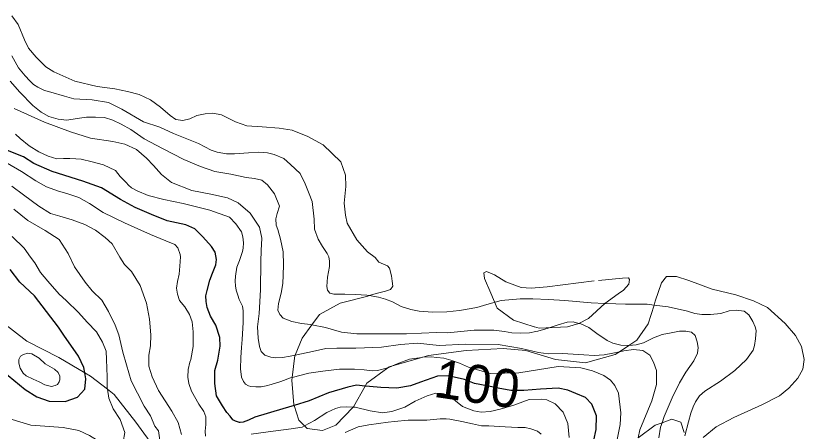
# Model space of a CAD drawing. Extents: x 474.5 to 500, y 7345.7 to 7373.4.
# Drawn here: x 486.724 to 488.382, y 7367.094 to 7367.969 of the extents above; entities that cross this region are included whole.
import ezdxf
from ezdxf.enums import TextEntityAlignment as Align

# ---------------------------------------------------------------- set-up
doc = ezdxf.new("R2010")
doc.units = 0
doc.header["$LTSCALE"] = 0.032
doc.linetypes.add('SHORT_DASHED', pattern=[2.7, 1.5, -1.2])
for name, color, linetype, lineweight in [('1', 7, 'Continuous', 25), ('16', 7, 'SHORT_DASHED', 13), ('2', 7, 'Continuous', 13)]:
    doc.layers.add(name, color=color, linetype=linetype, lineweight=lineweight)
doc.layers.add('61', color=7, linetype='Continuous')

msp = doc.modelspace()

# ---------------------------------------------------------------- linework, layer by layer
at = {"layer": '1'}
for points in [[(487.9397, 7367.0753), (487.9444, 7367.0977), (487.9451, 7367.127), (487.9356, 7367.1516), (487.9219, 7367.1652), (487.9015, 7367.1734), (487.8851, 7367.1809), (487.8647, 7367.185), (487.8272, 7367.1829), (487.7925, 7367.1802), (487.7652, 7367.1802), (487.7386, 7367.185), (487.7148, 7367.1897), (487.6888, 7367.1947), (487.6677, 7367.2034), (487.633, 7367.2109), (487.6112, 7367.2102), (487.575, 7367.1979), (487.5539, 7367.1897), (487.5253, 7367.185), (487.4919, 7367.1863), (487.468, 7367.1884), (487.4586, 7367.1893), (487.4408, 7367.1911), (487.4224, 7367.187), (487.3815, 7367.1748), (487.3406, 7367.1584), (487.309, 7367.1487), (487.2854, 7367.1414), (487.2268, 7367.1236), (487.2132, 7367.1175), (487.2023, 7367.1134), (487.1954, 7367.1127), (487.1941, 7367.1127), (487.1859, 7367.1155), (487.1804, 7367.1182), (487.175, 7367.1257), (487.168, 7367.1335), (487.1586, 7367.1475), (487.1457, 7367.1686), (487.1423, 7367.1945), (487.1423, 7367.2225), (487.1491, 7367.2436), (487.1539, 7367.2736), (487.1532, 7367.292), (487.1443, 7367.3179), (487.1334, 7367.3363), (487.1266, 7367.3547), (487.1239, 7367.3676), (487.1232, 7367.3792), (487.1266, 7367.3908), (487.1321, 7367.4126), (487.1375, 7367.4269), (487.1443, 7367.4446), (487.1457, 7367.4562), (487.143, 7367.4712), (487.1355, 7367.4835), (487.1171, 7367.5039), (487.1007, 7367.5203), (487.0816, 7367.5291), (487.0421, 7367.5373), (487.0094, 7367.551), (486.9746, 7367.5653), (486.944, 7367.5823), (486.9037, 7367.6068), (486.8649, 7367.6212), (486.8002, 7367.6409), (486.762, 7367.658), (486.7402, 7367.6723), (486.6809, 7367.6954)], [(486.6958, 7367.2218), (486.7433, 7367.1823), (486.7683, 7367.1667), (486.7941, 7367.1578), (486.8278, 7367.157), (486.8539, 7367.1658), (486.8688, 7367.183), (486.8714, 7367.2045), (486.8689, 7367.2175), (486.8667, 7367.2284), (486.8555, 7367.2526), (486.8246, 7367.2963), (486.8137, 7367.3135), (486.7631, 7367.3793), (486.7321, 7367.4081), (486.712, 7367.4346)]]:
    msp.add_lwpolyline(points, dxfattribs=at)
at = {"layer": '16'}
for points in [[(487.4637, 7367.472), (487.441, 7367.4973), (487.421, 7367.5321), (487.417, 7367.5494), (487.4143, 7367.5748), (487.4183, 7367.6095), (487.4175, 7367.6333), (487.4076, 7367.6616), (487.3702, 7367.6976), (487.3382, 7367.715), (487.3048, 7367.7283), (487.2781, 7367.7323), (487.2421, 7367.735), (487.21, 7367.7377), (487.186, 7367.7457), (487.1566, 7367.7604), (487.1379, 7367.7644), (487.1219, 7367.763), (487.1045, 7367.759), (487.0898, 7367.7524), (487.0752, 7367.7484), (487.0605, 7367.751), (487.0485, 7367.759), (487.0284, 7367.7764), (487.0071, 7367.7924), (486.983, 7367.8031), (486.959, 7367.8098), (486.9323, 7367.8151), (486.8949, 7367.8205), (486.8482, 7367.8311), (486.8041, 7367.8512), (486.7868, 7367.8618), (486.7667, 7367.8819), (486.7507, 7367.9006), (486.7419, 7367.9186), (486.7287, 7367.9511), (486.7154, 7367.9692)], [(487.5057, 7367.4425), (487.4873, 7367.4503), (487.4797, 7367.46), (487.4637, 7367.472)], [(488.0926, 7367.4199), (488.0819, 7367.407), (488.0689, 7367.3681), (488.0663, 7367.3598), (488.0538, 7367.3206), (488.03, 7367.286), (488.013, 7367.2747), (487.9935, 7367.2616), (487.9847, 7367.2558), (487.922, 7367.2385), (487.8594, 7367.245), (487.7968, 7367.2644), (487.7493, 7367.2688), (487.6715, 7367.2644), (487.5916, 7367.2536), (487.5781, 7367.2497), (487.5164, 7367.2319), (487.5095, 7367.2299), (487.5063, 7367.2275), (487.462, 7367.1953), (487.4586, 7367.1893), (487.4339, 7367.1456), (487.4334, 7367.145), (487.3972, 7367.1068), (487.3691, 7367.096), (487.3367, 7367.1003), (487.3314, 7367.1056), (487.3194, 7367.1176), (487.309, 7367.1487), (487.3086, 7367.15), (487.3043, 7367.2018), (487.305, 7367.2074), (487.3108, 7367.2536), (487.3112, 7367.2545), (487.3259, 7367.2904), (487.3466, 7367.3184), (487.3626, 7367.34), (487.4058, 7367.3638), (487.4641, 7367.3789), (487.4673, 7367.3798), (487.4849, 7367.3849), (487.5016, 7367.3892), (487.5119, 7367.3929), (487.5166, 7367.3995), (487.5152, 7367.4103), (487.5138, 7367.4212), (487.5096, 7367.438), (487.5057, 7367.4425)], [(487.7227, 7367.3851), (487.7094, 7367.4159), (487.7083, 7367.4276), (487.7137, 7367.4307)], [(487.7137, 7367.4307), (487.7307, 7367.4239), (487.7548, 7367.4092), (487.7868, 7367.3972), (487.8082, 7367.3959), (487.8415, 7367.3985), (487.9497, 7367.4119), (487.9999, 7367.4163), (488.0126, 7367.4174)], [(488.0126, 7367.4174), (488.0148, 7367.414), (488.0132, 7367.4038), (488.0023, 7367.391), (487.9907, 7367.3833), (487.9626, 7367.3635)], [(488.17, 7367.0808), (488.1967, 7367.1035), (488.2341, 7367.1235), (488.2928, 7367.1502), (488.3302, 7367.1689), (488.3502, 7367.1849), (488.3689, 7367.2063), (488.3796, 7367.225), (488.3823, 7367.245), (488.3769, 7367.273), (488.3636, 7367.2957), (488.3422, 7367.3211), (488.3048, 7367.3545), (488.2755, 7367.3692), (488.2381, 7367.3812), (488.1887, 7367.3932), (488.1393, 7367.4119), (488.1139, 7367.4199), (488.0926, 7367.4199)], [(487.8142, 7367.3138), (487.7706, 7367.3283), (487.7367, 7367.3532), (487.7227, 7367.3851)], [(487.9626, 7367.3635), (487.9285, 7367.3314), (487.9085, 7367.3214)], [(486.6974, 7367.3228), (486.7471, 7367.2839), (486.814, 7367.2493), (486.8689, 7367.2175), (486.881, 7367.2104), (486.9165, 7367.1826), (486.9306, 7367.1716), (486.976, 7367.1132), (487.0235, 7367.0484), (487.0309, 7367.0365), (487.0575, 7366.9935), (487.0831, 7366.9551), (487.1102, 7366.9431), (487.1531, 7366.9356), (487.1606, 7366.9343), (487.2379, 7366.9445), (487.3718, 7366.9623), (487.4094, 7366.9711), (487.4378, 7366.976), (487.5197, 7366.9903)], [(487.9085, 7367.3214), (487.8843, 7367.3138), (487.8247, 7367.3115), (487.815, 7367.3138), (487.8142, 7367.3138)], [(488.0331, 7367.0803), (488.0689, 7367.1068), (488.0832, 7367.1121), (488.1035, 7367.1197), (488.1229, 7367.1132), (488.1294, 7367.0916)]]:
    msp.add_lwpolyline(points, dxfattribs=at)
at = {"layer": '2'}
for points in [[(486.7151, 7367.8848), (486.7292, 7367.8593), (486.7434, 7367.8428), (486.753, 7367.8322), (486.761, 7367.8246), (486.7699, 7367.8189), (486.7842, 7367.812), (486.7974, 7367.808), (486.8259, 7367.8), (486.8461, 7367.7944), (486.8847, 7367.7924), (486.9185, 7367.7864), (486.947, 7367.7722), (486.9925, 7367.746), (487.027, 7367.7348), (487.0558, 7367.7215), (487.1083, 7367.7003), (487.1345, 7367.686), (487.1474, 7367.6817), (487.1673, 7367.6781), (487.184, 7367.6781), (487.2135, 7367.6804), (487.235, 7367.6821), (487.2533, 7367.6808), (487.2672, 7367.6771), (487.2874, 7367.6685), (487.3018, 7367.6562), (487.3223, 7367.6367), (487.3326, 7367.6155), (487.3412, 7367.5943), (487.3473, 7367.5781), (487.3513, 7367.541), (487.352, 7367.5201), (487.3601, 7367.4986), (487.3687, 7367.4834), (487.379, 7367.4688), (487.3823, 7367.4618), (487.384, 7367.4522), (487.384, 7367.4413), (487.3793, 7367.4187), (487.3783, 7367.3992), (487.3795, 7367.3916), (487.3844, 7367.385), (487.3927, 7367.383), (487.4026, 7367.383), (487.4159, 7367.383), (487.4381, 7367.3823), (487.4619, 7367.3806), (487.4673, 7367.3798), (487.4868, 7367.3767), (487.5012, 7367.3727), (487.5161, 7367.3668), (487.5343, 7367.3572), (487.5545, 7367.3505), (487.5724, 7367.3469), (487.6009, 7367.3452), (487.6302, 7367.3459), (487.657, 7367.3485), (487.6935, 7367.3548), (487.7148, 7367.361), (487.745, 7367.3697), (487.7844, 7367.3733)], [(488.1572, 7367.2824), (488.1528, 7367.2956), (488.1453, 7367.3027), (488.133, 7367.3053), (488.1202, 7367.3053), (488.1021, 7367.3018), (488.0836, 7367.2978), (488.0651, 7367.2908), (488.0439, 7367.2802), (488.0289, 7367.2762), (488.013, 7367.2747), (488.0113, 7367.2745), (487.9968, 7367.2758), (487.98, 7367.2798), (487.9677, 7367.2855), (487.9461, 7367.3), (487.9293, 7367.3128), (487.9126, 7367.3203), (487.9085, 7367.3214), (487.8962, 7367.3247), (487.8839, 7367.3243), (487.8645, 7367.3181), (487.8433, 7367.3111), (487.8217, 7367.3049), (487.818, 7367.3042), (487.8041, 7367.3014), (487.7856, 7367.3005), (487.7671, 7367.3018), (487.7517, 7367.304), (487.7292, 7367.3071), (487.6877, 7367.3071), (487.6322, 7367.3014), (487.6084, 7367.3022), (487.5453, 7367.2996), (487.4783, 7367.2992), (487.4409, 7367.2996), (487.4091, 7367.3031), (487.3756, 7367.3124), (487.3466, 7367.3184), (487.3439, 7367.319), (487.3245, 7367.3212), (487.3042, 7367.3256), (487.2861, 7367.3322), (487.279, 7367.34), (487.2747, 7367.349), (487.2764, 7367.3635), (487.2817, 7367.3851), (487.2853, 7367.4054), (487.2861, 7367.4226), (487.287, 7367.4446), (487.2861, 7367.472), (487.2804, 7367.4984), (487.2747, 7367.5191), (487.2716, 7367.5284), (487.2707, 7367.5416), (487.2738, 7367.5531), (487.2786, 7367.5685), (487.2681, 7367.5941), (487.2535, 7367.6135), (487.2412, 7367.6227), (487.2262, 7367.6267), (487.2081, 7367.6289), (487.1759, 7367.6359), (487.1424, 7367.6412), (487.112, 7367.6518), (487.0772, 7367.6664), (487.0322, 7367.6897), (486.9939, 7367.71), (486.9661, 7367.7294), (486.9454, 7367.7409), (486.9277, 7367.7492), (486.9101, 7367.755), (486.8916, 7367.7559), (486.8726, 7367.7559), (486.8532, 7367.7528), (486.8312, 7367.7492), (486.8131, 7367.7514), (486.7933, 7367.7572), (486.7774, 7367.766), (486.7598, 7367.7805), (486.732, 7367.8083), (486.7117, 7367.8312)], [(487.9797, 7367.2584), (487.9613, 7367.2553), (487.9402, 7367.254), (487.9187, 7367.2553), (487.8738, 7367.258), (487.8446, 7367.2575), (487.8236, 7367.2602), (487.7877, 7367.2688), (487.7387, 7367.2768), (487.6696, 7367.2777), (487.6144, 7367.2746), (487.5691, 7367.2795), (487.5327, 7367.2768), (487.4928, 7367.2715), (487.4389, 7367.2692), (487.399, 7367.2692), (487.3757, 7367.2688), (487.3478, 7367.2625), (487.3112, 7367.2545), (487.3007, 7367.2522), (487.285, 7367.2495), (487.2698, 7367.2486), (487.2603, 7367.2499), (487.2478, 7367.2548), (487.2397, 7367.2625), (487.2365, 7367.2724), (487.2339, 7367.2903), (487.2325, 7367.3141), (487.2356, 7367.3419), (487.2388, 7367.3917), (487.2392, 7367.4519), (487.2401, 7367.4748), (487.241, 7367.5008), (487.2361, 7367.5237), (487.2168, 7367.5533), (487.1912, 7367.5753), (487.1688, 7367.5856), (487.1338, 7367.5937), (487.0938, 7367.6009), (487.0516, 7367.6179), (487.0301, 7367.635), (487.0131, 7367.6538), (486.9987, 7367.6695), (486.9776, 7367.6875), (486.9529, 7367.6991), (486.9278, 7367.7045), (486.8811, 7367.7117), (486.8389, 7367.7247), (486.7842, 7367.7449), (486.72, 7367.7741)], [(487.6391, 7367.2439), (487.6244, 7367.2479), (487.6093, 7367.2496), (487.5976, 7367.2509), (487.5795, 7367.2499), (487.5781, 7367.2497), (487.5518, 7367.2459), (487.526, 7367.2362), (487.5164, 7367.2319), (487.5073, 7367.2278), (487.5063, 7367.2275), (487.4845, 7367.2221), (487.4738, 7367.2215), (487.4568, 7367.2235), (487.436, 7367.2248), (487.4049, 7367.2252), (487.3698, 7367.2211), (487.3403, 7367.2168), (487.305, 7367.2074), (487.3015, 7367.2065), (487.2811, 7367.1988), (487.2613, 7367.1927), (487.2506, 7367.1901), (487.2399, 7367.1881), (487.2289, 7367.1877), (487.2185, 7367.1884), (487.2131, 7367.1897), (487.2071, 7367.1931), (487.2028, 7367.1988), (487.1984, 7367.2078), (487.1964, 7367.2255), (487.1971, 7367.2493), (487.1984, 7367.2707), (487.2001, 7367.2878), (487.2023, 7367.3232), (487.2023, 7367.3476), (487.2006, 7367.3576), (487.1939, 7367.372), (487.1906, 7367.3807), (487.1876, 7367.3911), (487.1859, 7367.4008), (487.1852, 7367.4105), (487.1856, 7367.4209), (487.189, 7367.4397), (487.1945, 7367.4541), (487.2006, 7367.4725), (487.2022, 7367.4799), (487.2026, 7367.4913), (487.2016, 7367.5036), (487.1982, 7367.514), (487.1865, 7367.5308), (487.173, 7367.5451), (487.1322, 7367.5595), (487.076, 7367.5736), (487.0352, 7367.582), (487.0023, 7367.591), (486.9792, 7367.6004), (486.9672, 7367.6068), (486.9608, 7367.6125), (486.9558, 7367.6181), (486.9434, 7367.6305), (486.9332, 7367.6431), (486.9083, 7367.6551), (486.8842, 7367.6618), (486.8615, 7367.6669), (486.8501, 7367.6682), (486.8371, 7367.6685), (486.824, 7367.6685), (486.8103, 7367.6681), (486.7921, 7367.6733), (486.7721, 7367.6823), (486.7517, 7367.695), (486.7333, 7367.7107), (486.7232, 7367.7198)], [(487.1228, 7367.0838), (487.122, 7367.0945), (487.1233, 7367.1086), (487.1233, 7367.1245), (487.1194, 7367.1361), (487.1091, 7367.1515), (487.0932, 7367.179), (487.0877, 7367.1948), (487.0859, 7367.2081), (487.0864, 7367.2244), (487.0902, 7367.2399), (487.0919, 7367.2454), (487.0967, 7367.2729), (487.0971, 7367.3033), (487.0949, 7367.3244), (487.0889, 7367.3402), (487.0791, 7367.3565), (487.0679, 7367.3698), (487.0636, 7367.3831), (487.0619, 7367.3955), (487.0636, 7367.4093), (487.0671, 7367.4247), (487.0688, 7367.4419), (487.0701, 7367.4612), (487.0696, 7367.4667), (487.0649, 7367.4805), (487.0581, 7367.4873), (487.0396, 7367.495), (487.007, 7367.5088), (486.9526, 7367.5328), (486.9075, 7367.5551), (486.8788, 7367.5739), (486.8565, 7367.5864), (486.8312, 7367.595), (486.8136, 7367.5997), (486.7883, 7367.6087), (486.7656, 7367.6215), (486.736, 7367.6413), (486.7056, 7367.6589)], [(487.072, 7367.0877), (487.0653, 7367.1127), (487.0523, 7367.1366), (487.0237, 7367.1802), (487.0107, 7367.2088), (487.0039, 7367.2313), (487.0039, 7367.2545), (487.0073, 7367.2743), (487.008, 7367.2974), (487.0053, 7367.3301), (486.9985, 7367.3642), (486.9855, 7367.401), (486.9671, 7367.4303), (486.9521, 7367.4453), (486.9426, 7367.461), (486.9262, 7367.4889), (486.9119, 7367.5019), (486.8915, 7367.5176), (486.869, 7367.5298), (486.8424, 7367.5394), (486.8165, 7367.5475), (486.7967, 7367.553), (486.7722, 7367.568), (486.7402, 7367.5918), (486.7156, 7367.6102)], [(487.031, 7367.0459), (487.0238, 7367.0953), (487.016, 7367.1049), (487.0071, 7367.1267), (486.9937, 7367.1468), (486.9801, 7367.1741), (486.9664, 7367.2007), (486.9569, 7367.234), (486.9487, 7367.2606), (486.9406, 7367.2974), (486.9331, 7367.3179), (486.9187, 7367.3465), (486.9044, 7367.3704), (486.8847, 7367.3901), (486.8697, 7367.4085), (486.8472, 7367.4405), (486.8342, 7367.4685), (486.8152, 7367.4978), (486.7852, 7367.5169), (486.749, 7367.538), (486.7197, 7367.5619)], [(486.914, 7367.2632), (486.9061, 7367.2819), (486.8935, 7367.3038), (486.874, 7367.3241), (486.856, 7367.3445), (486.8294, 7367.3695), (486.8153, 7367.3828), (486.791, 7367.4102), (486.7754, 7367.4282), (486.7637, 7367.4486), (486.755, 7367.4611), (486.7417, 7367.4799), (486.7159, 7367.5041)], [(487.7844, 7367.3733), (487.8116, 7367.3733), (487.8444, 7367.3714), (487.8785, 7367.3694), (487.9341, 7367.3644), (487.9626, 7367.3635), (487.9656, 7367.3634), (488.0063, 7367.3621), (488.0517, 7367.3617), (488.0663, 7367.3598), (488.0958, 7367.3561), (488.1367, 7367.3471), (488.1523, 7367.3425), (488.1668, 7367.3398), (488.185, 7367.3398), (488.2066, 7367.3425), (488.2241, 7367.3481), (488.239, 7367.3494), (488.2563, 7367.3471), (488.2655, 7367.3395), (488.2741, 7367.3253), (488.2794, 7367.3143), (488.2811, 7367.3064), (488.2796, 7367.2888), (488.2776, 7367.2746), (488.2746, 7367.265), (488.2607, 7367.2454), (488.2364, 7367.2225), (488.2065, 7367.2), (488.1734, 7367.1785), (488.162, 7367.1689), (488.1534, 7367.156), (488.1487, 7367.146), (488.1441, 7367.1324), (488.1388, 7367.1142), (488.131, 7367.0847)], [(488.0761, 7367.0801), (488.0801, 7367.1025), (488.0832, 7367.1121), (488.0876, 7367.1255), (488.1048, 7367.1647), (488.1197, 7367.196), (488.1334, 7367.2189), (488.1502, 7367.2423), (488.1577, 7367.2586), (488.1594, 7367.2709), (488.1572, 7367.2824)], [(488.0331, 7367.0803), (488.0367, 7367.0973), (488.0619, 7367.1584), (488.0717, 7367.1929), (488.0717, 7367.2221), (488.0654, 7367.24), (488.0574, 7367.2548), (488.043, 7367.2643), (488.0233, 7367.2665), (488.0026, 7367.2638), (487.9935, 7367.2616), (487.9797, 7367.2584)], [(486.7162, 7367.1193), (486.7557, 7367.1071), (486.8234, 7367.1019), (486.8561, 7367.0956), (486.8789, 7367.085), (486.9116, 7367.0647), (486.9231, 7367.0613), (486.939, 7367.0621), (486.9497, 7367.0717), (486.9528, 7367.0915), (486.9431, 7367.1189), (486.9288, 7367.1413), (486.9193, 7367.1636), (486.9165, 7367.1826), (486.9162, 7367.185), (486.9162, 7367.2086), (486.9146, 7367.2451), (486.914, 7367.2632)], [(487.9821, 7367.0426), (487.9953, 7367.1087), (487.9966, 7367.1327), (487.9919, 7367.1744), (487.9836, 7367.1905), (487.9747, 7367.2016), (487.9607, 7367.2118), (487.937, 7367.2216), (487.9123, 7367.228), (487.8644, 7367.2303), (487.7817, 7367.2172), (487.7213, 7367.2162), (487.6762, 7367.2292), (487.6574, 7367.2375), (487.6391, 7367.2439)], [(487.6872, 7367.1369), (487.6636, 7367.1464), (487.634, 7367.1704), (487.6216, 7367.1734), (487.607, 7367.1743), (487.5894, 7367.1691), (487.5641, 7367.1575), (487.5422, 7367.1451), (487.5148, 7367.1357), (487.4955, 7367.1331), (487.4693, 7367.1369), (487.438, 7367.1447), (487.4334, 7367.145), (487.4204, 7367.146), (487.4063, 7367.1447), (487.3964, 7367.1421), (487.3784, 7367.1335), (487.3523, 7367.1172), (487.3314, 7367.1056), (487.3261, 7367.1026), (487.3029, 7367.0992), (487.2652, 7367.0945), (487.2189, 7367.0881)], [(487.8879, 7367.0808), (487.8849, 7367.1104), (487.8755, 7367.1344), (487.8583, 7367.152), (487.8407, 7367.1605), (487.8291, 7367.1618), (487.8034, 7367.161), (487.7717, 7367.1494), (487.7429, 7367.1404), (487.7219, 7367.1357), (487.7026, 7367.1344), (487.6872, 7367.1369)], [(487.8286, 7367.0882), (487.8211, 7367.0943), (487.8074, 7367.0991), (487.7952, 7367.1018), (487.7795, 7367.1018), (487.7529, 7367.1032), (487.7188, 7367.1059), (487.7032, 7367.1059), (487.6848, 7367.11), (487.6623, 7367.1148), (487.6371, 7367.1196), (487.6289, 7367.1202), (487.6166, 7367.1202), (487.5887, 7367.1175), (487.5492, 7367.1175), (487.5205, 7367.1148), (487.5069, 7367.1134), (487.4667, 7367.108), (487.4442, 7367.1032), (487.4163, 7367.0916)]]:
    msp.add_lwpolyline(points, dxfattribs=at)
msp.add_lwpolyline([(486.7856, 7367.2365), (486.773, 7367.2482), (486.7574, 7367.2576), (486.7488, 7367.2584), (486.7402, 7367.2561), (486.7339, 7367.2522), (486.73, 7367.2451), (486.73, 7367.2373), (486.7331, 7367.2271), (486.7394, 7367.2169), (486.7457, 7367.2107), (486.7605, 7367.2036), (486.773, 7367.1982), (486.7848, 7367.1919), (486.7989, 7367.1888), (486.8063, 7367.1903), (486.8114, 7367.1928), (486.8153, 7367.1982), (486.8167, 7367.2027), (486.8165, 7367.21), (486.8129, 7367.2177), (486.8051, 7367.2248)], close=True, dxfattribs=at)

# ---------------------------------------------------------------- texts
at = {"layer": '61'}
msp.add_text('100', height=0.08, rotation=351.784, dxfattribs=at).set_placement((487.6887, 7367.1543), align=Align.CENTER)

doc.saveas('drawing.dxf')
